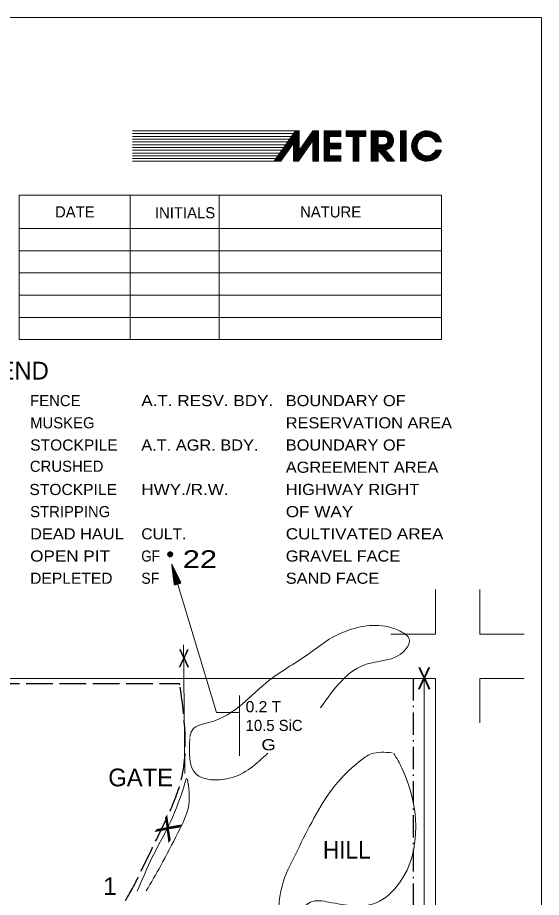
# Model space of a CAD drawing. Extents: x -496 to 480, y -450 to 700.
# Drawn here: x 214.3 to 450, y 303.7 to 700 of the extents above; entities that cross this region are included whole.
import ezdxf
from ezdxf.enums import TextEntityAlignment as Align

# ---------------------------------------------------------------- set-up
doc = ezdxf.new("R2010")
doc.units = 0
doc.header["$LTSCALE"] = 2
doc.linetypes.add('DOT_DASHED', pattern=[7.7, 5, -1.2, 0.3, -1.2])
doc.linetypes.add('LONG_DASHED', pattern=[7.5, 6, -1.5])
for name, color, linetype, lineweight in [('1', 7, 'Continuous', 13), ('2', 7, 'Continuous', 35), ('3', 7, 'Continuous', 13), ('4', 7, 'Continuous', 25)]:
    doc.layers.add(name, color=color, linetype=linetype, lineweight=lineweight)

msp = doc.modelspace()

# ---------------------------------------------------------------- linework, layer by layer
at = {"layer": '1'}
for p, q in [((339.376, 648.989), (265.976, 648.989)), ((338.501, 647.739), (265.976, 647.739)), ((337.626, 646.489), (265.976, 646.489)), ((329.726, 635.239), (339.376, 648.989)), ((340.976, 640.064), (347.226, 648.989)), ((349.726, 648.989), (347.226, 648.989)), ((349.726, 635.239), (349.726, 648.989)), ((354.726, 646.489), (354.726, 643.364)), ((362.226, 648.989), (362.226, 646.489)), ((362.226, 646.489), (365.351, 646.489)), ((367.851, 646.489), (370.976, 646.489)), ((379.026, 648.989), (373.476, 648.989)), ((376.601, 646.489), (379.151, 646.489)), ((376.601, 642.739), (376.601, 646.489)), ((336.751, 645.239), (265.976, 645.239)), ((335.876, 643.989), (265.976, 643.989)), ((335.001, 642.739), (265.976, 642.739)), ((332.776, 635.239), (338.476, 643.364)), ((338.476, 635.239), (338.476, 643.389)), ((340.676, 635.264), (347.226, 644.614)), ((347.226, 635.239), (347.226, 644.614)), ((376.601, 642.739), (379.151, 642.739)), ((402.426, 643.989), (405.076, 643.989)), ((334.126, 641.489), (265.976, 641.489)), ((333.251, 640.239), (265.976, 640.239)), ((332.376, 638.989), (265.976, 638.989)), ((354.726, 640.864), (354.726, 637.739)), ((376.601, 640.239), (380.726, 635.239)), ((376.601, 635.239), (376.601, 640.239)), ((379.801, 640.289), (383.951, 635.239)), ((402.426, 640.239), (405.101, 640.239)), ((331.501, 637.739), (265.976, 637.739)), ((330.626, 636.489), (265.976, 636.489)), ((329.726, 635.239), (265.976, 635.239)), ((329.726, 635.239), (332.776, 635.239)), ((338.476, 635.239), (340.676, 635.239)), ((349.726, 635.239), (347.226, 635.239)), ((352.226, 635.239), (359.726, 635.239)), ((380.726, 635.239), (383.951, 635.239)), ((404.983, 619.973), (214.983, 619.973)), ((214.983, 619.973), (214.983, 554.973)), ((264.983, 619.973), (264.983, 554.973)), ((304.983, 619.973), (304.983, 554.973)), ((404.983, 554.973), (404.983, 619.973)), ((214.983, 604.973), (404.983, 604.973)), ((214.983, 594.973), (404.983, 594.973)), ((214.983, 584.973), (404.983, 584.973)), ((214.983, 574.973), (404.983, 574.973)), ((214.983, 564.973), (404.983, 564.973)), ((214.983, 554.973), (404.983, 554.973)), ((402.281, 422.339), (402.281, 442.339)), ((422.281, 422.339), (422.281, 442.339)), ((402.281, 422.339), (382.281, 422.339)), ((422.281, 422.339), (442.281, 422.339)), ((422.281, 402.339), (442.281, 402.339)), ((422.281, 402.339), (422.281, 382.339))]:
    msp.add_line(p, q, dxfattribs=at)
for points in [[(449.983, -450.027), (449.983, 399.973), (449.983, 699.973), (-450.017, 699.973), (-450.017, 49.973), (-450.017, -450.027)], [(329.901, 635.339), (339.401, 648.889), (340.901, 648.889), (340.901, 639.839), (347.251, 648.839), (349.626, 648.889), (349.676, 635.339), (347.351, 635.314), (347.301, 644.789), (340.576, 635.339), (338.576, 635.314), (338.576, 643.539), (332.701, 635.339), (330.076, 635.314), (339.501, 648.739), (340.801, 648.739), (340.776, 639.664), (347.276, 648.664), (349.526, 648.739), (349.651, 635.564), (347.501, 635.464), (347.426, 644.989), (340.526, 635.489), (338.726, 635.439), (338.676, 643.764), (332.651, 635.464), (330.301, 635.439), (339.576, 648.539), (340.651, 648.564), (340.651, 639.489), (347.351, 648.489), (349.301, 648.564), (349.476, 635.739), (347.726, 635.639), (347.626, 645.314), (340.451, 635.714), (338.926, 635.639), (338.876, 644.139), (332.501, 635.689), (330.701, 635.639)], [(330.701, 635.639), (339.651, 648.239), (340.326, 648.264), (340.476, 639.239), (347.526, 648.239), (349.126, 648.289), (349.226, 635.939), (348.001, 635.939), (347.851, 645.664), (340.326, 635.989), (339.151, 635.864), (339.126, 644.464), (332.401, 635.939), (331.076, 635.839), (339.651, 647.914), (340.151, 647.914), (340.251, 638.889), (347.601, 647.964), (348.926, 648.014), (349.026, 636.164), (348.251, 636.139), (348.051, 646.014), (340.226, 636.239), (339.351, 636.089), (339.326, 644.789), (332.226, 636.164), (331.476, 636.064), (339.701, 647.664), (339.926, 647.689), (340.126, 638.764), (347.751, 647.839), (348.701, 647.739), (348.826, 636.364), (348.476, 636.364), (348.176, 646.314), (340.126, 636.464), (339.551, 636.339), (339.426, 645.114), (332.201, 636.339), (331.851, 636.289)], [(331.851, 636.289), (339.701, 647.264), (339.926, 638.564), (347.826, 647.614), (348.451, 647.589), (348.701, 636.589), (348.251, 646.639), (340.126, 636.689), (339.726, 636.589), (339.576, 645.539), (332.301, 636.639), (339.526, 646.714), (339.576, 645.814), (335.101, 640.239), (339.401, 646.164), (339.401, 645.914), (338.176, 644.289)], [(340.976, 640.039), (340.976, 648.989), (339.376, 648.989)], [(339.901, 638.414), (339.926, 636.839), (348.276, 646.889), (348.326, 647.439), (347.951, 647.439), (340.126, 638.539), (340.151, 637.314), (348.176, 647.064), (348.051, 647.214), (340.326, 638.539), (340.401, 637.839), (347.851, 646.839), (340.501, 638.639), (340.526, 638.389), (344.426, 642.914)], [(352.226, 635.239), (352.226, 648.989), (359.726, 648.989)], [(352.376, 648.914), (359.651, 648.864), (359.676, 646.614), (354.626, 646.589), (354.626, 643.289), (359.651, 643.289), (359.651, 640.989), (354.651, 640.939), (354.626, 637.614), (359.676, 637.639), (359.651, 635.339), (352.351, 635.314), (352.376, 648.789), (359.551, 648.739), (359.551, 646.764), (354.501, 646.714), (354.501, 643.214), (359.551, 643.164), (359.551, 641.114), (354.551, 641.064), (354.526, 637.439), (359.551, 637.514), (359.501, 635.439), (352.501, 635.439), (352.576, 648.639), (359.401, 648.564), (359.426, 646.914), (354.376, 646.839), (354.351, 643.064), (359.426, 643.039), (359.376, 641.289), (354.401, 641.239), (354.376, 637.239), (359.401, 637.339), (359.376, 635.589), (352.701, 635.614), (352.726, 648.439), (359.226, 648.414), (359.251, 647.064), (354.251, 647.039)], [(354.251, 647.039), (354.176, 642.864), (359.251, 642.864), (359.176, 641.439), (354.251, 641.389), (354.201, 637.064), (359.201, 637.114), (359.176, 635.739), (352.926, 635.814), (352.976, 648.214), (359.026, 648.239), (359.076, 647.289), (354.076, 647.214), (354.001, 642.689), (359.051, 642.664), (359.026, 641.639), (354.076, 641.564), (354.026, 636.864), (359.051, 636.939), (359.026, 635.989), (353.126, 636.039), (353.226, 647.989), (358.801, 648.039), (358.826, 647.464), (353.926, 647.389), (353.851, 642.489), (358.876, 642.539), (358.801, 641.814), (353.951, 641.689), (353.851, 636.714), (358.901, 636.764), (358.901, 636.214), (353.351, 636.214), (353.476, 647.714), (358.601, 647.889), (358.626, 647.639), (353.776, 647.514), (353.751, 642.364), (358.626, 642.389), (358.601, 642.014)], [(358.601, 642.014), (353.826, 641.864), (353.726, 636.564), (358.701, 636.639), (358.701, 636.389), (353.551, 636.439), (353.626, 641.989), (358.376, 642.164), (358.326, 642.289), (353.576, 642.264), (353.676, 647.564)], [(359.726, 648.989), (359.726, 646.489), (354.726, 646.489)], [(370.976, 646.489), (370.976, 648.989), (362.226, 648.989)], [(362.351, 648.864), (370.851, 648.889), (370.851, 646.639), (367.701, 646.639), (367.751, 635.414), (365.451, 635.314), (365.451, 646.564), (362.351, 646.589), (362.351, 648.764), (370.801, 648.789), (370.726, 646.789), (367.601, 646.764), (367.676, 635.539), (365.576, 635.414), (365.626, 646.739), (362.476, 646.739), (362.476, 648.639), (370.626, 648.639), (370.576, 646.989), (367.426, 646.864), (367.526, 635.739), (365.751, 635.614), (365.776, 646.864), (362.701, 646.939), (362.726, 648.439), (370.451, 648.489), (370.376, 647.114), (367.276, 646.989), (367.376, 635.914), (365.901, 635.789), (365.951, 647.064), (362.901, 647.114), (362.901, 648.264), (370.201, 648.289), (370.201, 647.364), (367.076, 647.189), (367.226, 636.114), (366.126, 635.989), (366.101, 647.264), (363.101, 647.314)], [(363.101, 647.314), (363.151, 648.089), (369.976, 648.164), (369.926, 647.489), (366.876, 647.364), (367.026, 636.339), (366.351, 636.239), (366.276, 647.439), (363.326, 647.514), (363.401, 647.939), (369.751, 648.039), (369.701, 647.714), (366.726, 647.539), (366.851, 636.564), (366.476, 636.489), (366.426, 647.664), (363.701, 647.664), (363.751, 647.839), (369.451, 647.914), (369.426, 647.814), (366.601, 647.664), (366.626, 636.689)], [(367.851, 646.489), (367.851, 635.239), (365.351, 635.239), (365.351, 646.489)], [(373.476, 648.989), (373.476, 635.239), (376.601, 635.239)], [(373.601, 648.914), (378.976, 648.889), (380.101, 648.739), (381.101, 648.364), (381.826, 647.789), (382.451, 647.189), (382.901, 646.414), (383.301, 645.389), (383.301, 644.439), (383.126, 643.214), (382.651, 642.314), (381.926, 641.489), (381.051, 640.889), (380.401, 640.639), (379.651, 640.389), (380.026, 639.714), (380.576, 639.189), (383.701, 635.339), (380.801, 635.314), (376.501, 640.464), (376.526, 635.339), (373.551, 635.314), (373.551, 648.864), (379.026, 648.789), (380.076, 648.639), (380.926, 648.314), (382.276, 647.214), (383.151, 645.364), (383.026, 643.314), (382.601, 642.464), (381.901, 641.614), (381.051, 640.989), (379.576, 640.464), (383.501, 635.414), (380.951, 635.439), (376.351, 640.739), (376.401, 635.489), (373.701, 635.439), (373.701, 648.739), (379.151, 648.664), (380.076, 648.489), (380.851, 648.189), (382.126, 647.139), (383.026, 645.389), (382.951, 643.539), (382.501, 642.564), (381.901, 641.739), (381.051, 641.114), (379.401, 640.614), (383.201, 635.564), (381.001, 635.564), (376.226, 640.889), (376.276, 635.614), (373.826, 635.539), (373.826, 648.614), (379.126, 648.489), (380.676, 648.089), (382.026, 647.139), (382.876, 645.439), (382.801, 643.664), (382.401, 642.664), (381.801, 641.889), (380.951, 641.189), (379.226, 640.764), (382.901, 635.689), (381.101, 635.689), (376.051, 641.064), (376.126, 635.789), (373.976, 635.689), (373.976, 648.439), (379.101, 648.364), (380.551, 647.989), (381.851, 647.089), (382.776, 645.439), (382.701, 643.764), (382.326, 642.889), (381.726, 642.064), (380.901, 641.339), (379.026, 640.939), (382.601, 635.789), (381.126, 635.814), (375.876, 641.239), (375.976, 635.939), (374.126, 635.864), (374.126, 648.239), (379.026, 648.239), (380.251, 647.914), (381.676, 647.014), (382.576, 645.414), (382.601, 643.914), (382.276, 642.989), (381.651, 642.214), (380.826, 641.514), (378.851, 641.064), (382.351, 635.939), (381.176, 635.989), (375.776, 641.514), (375.826, 636.089), (374.251, 636.014), (374.276, 648.039), (378.976, 648.114)], [(378.976, 648.114), (379.026, 648.114), (380.201, 647.764), (381.526, 646.939), (382.401, 645.489), (382.401, 643.964), (382.076, 643.114), (380.826, 641.764), (378.601, 641.264), (382.001, 636.114), (381.351, 636.114), (375.676, 641.789), (375.676, 636.264), (374.376, 636.189), (374.451, 647.864), (378.926, 647.939), (380.176, 647.689), (381.351, 646.914), (382.151, 645.414), (382.201, 644.014), (381.901, 643.214), (380.726, 641.989), (378.401, 641.389), (381.676, 636.314), (381.501, 636.189), (375.526, 642.064), (375.476, 636.414), (374.551, 636.339), (374.651, 647.739), (379.976, 647.614), (381.151, 646.914), (382.001, 645.414), (382.051, 644.139), (381.726, 643.339), (380.651, 642.139), (378.226, 641.589), (381.401, 636.464), (375.401, 642.364), (375.376, 636.614), (374.676, 636.539), (374.901, 647.589), (379.826, 647.414), (380.851, 646.889), (381.801, 645.439), (381.901, 644.389), (381.576, 643.539), (380.576, 642.414), (378.051, 641.739), (380.676, 637.364), (375.376, 642.614), (375.226, 636.739), (374.851, 636.739), (375.076, 647.339), (379.601, 647.314), (380.676, 646.839), (381.626, 645.414), (381.726, 644.464), (381.376, 643.589), (380.501, 642.589), (377.826, 641.864), (380.026, 638.189), (375.251, 642.889), (375.076, 636.939), (374.926, 636.989), (375.226, 647.189), (379.526, 647.139), (380.551, 646.714), (381.401, 645.414), (381.551, 644.614), (380.376, 642.739), (377.726, 642.039), (379.276, 639.239), (375.351, 643.039), (375.426, 646.989), (379.476, 646.989), (380.526, 646.639), (381.251, 645.489), (381.326, 644.614), (380.276, 642.914), (377.551, 642.239), (378.601, 640.139), (375.576, 643.139), (375.676, 646.839), (379.451, 646.839), (380.476, 646.514), (381.101, 645.414), (381.051, 644.489), (380.876, 645.464), (380.501, 646.039), (380.151, 646.339), (379.476, 646.514), (378.751, 646.639), (377.601, 646.614), (376.476, 646.614), (376.501, 642.714), (378.626, 642.664), (377.376, 642.339), (378.126, 640.764), (375.726, 643.164), (375.876, 646.714), (379.451, 646.714)], [(376.026, 646.614), (375.901, 643.214), (377.551, 641.614), (377.251, 642.364), (377.776, 642.614), (376.826, 642.614), (377.201, 642.164)], [(376.151, 646.564), (376.051, 643.314), (376.376, 643.064), (376.351, 646.564), (376.251, 643.389)], [(379.451, 646.714), (379.401, 646.739), (380.451, 646.289)], [(386.776, 648.839), (388.951, 648.864), (389.001, 635.364), (386.701, 635.364), (386.676, 648.739), (388.851, 648.764), (388.876, 635.489), (386.826, 635.439), (386.801, 648.614), (388.776, 648.639), (388.776, 635.664), (386.976, 635.589), (386.926, 648.464), (388.626, 648.464), (388.601, 635.764), (387.126, 635.764), (387.101, 648.364), (388.501, 648.364), (388.451, 635.939), (387.301, 635.964), (387.301, 648.214), (388.401, 648.214), (388.301, 636.089), (387.426, 636.089), (387.476, 648.064), (388.251, 648.039), (388.151, 636.214), (387.576, 636.214), (387.676, 647.914), (388.126, 647.889), (388.001, 636.339), (387.776, 636.389), (387.826, 647.764), (387.976, 647.714), (387.901, 636.539)], [(404.901, 644.089), (404.451, 645.189), (403.851, 646.164), (403.151, 646.914), (402.301, 647.639), (401.151, 648.289), (400.126, 648.614), (398.801, 648.814), (397.351, 648.689), (395.876, 648.339), (394.601, 647.639), (393.601, 646.764), (392.776, 645.664), (392.176, 644.564), (391.801, 642.964), (391.801, 641.264), (392.176, 639.789), (392.726, 638.564), (393.351, 637.739), (394.101, 637.014), (394.976, 636.389), (395.901, 635.914), (397.126, 635.489), (398.726, 635.389), (400.151, 635.589), (401.301, 635.989), (402.326, 636.564), (403.326, 637.414), (404.001, 638.264), (404.426, 639.139), (404.801, 640.064), (402.526, 640.089), (401.776, 638.989), (400.776, 638.289), (399.801, 637.814), (398.476, 637.564), (397.026, 637.839), (396.126, 638.289), (395.276, 638.939), (394.551, 639.939), (394.076, 641.189), (394.051, 642.814), (394.276, 643.889), (394.901, 644.889), (395.601, 645.614), (396.476, 646.164), (397.376, 646.489), (398.426, 646.614), (399.526, 646.489), (400.426, 646.214), (401.176, 645.764), (401.801, 645.239), (402.301, 644.664), (402.576, 644.139), (404.726, 644.164), (404.251, 645.214), (403.651, 646.164), (402.276, 647.489), (401.126, 648.114), (399.351, 648.614), (397.876, 648.564), (396.551, 648.339), (395.226, 647.814), (394.351, 647.264), (393.451, 646.339), (392.676, 645.139), (392.176, 643.939), (391.976, 642.239), (392.076, 640.689), (392.576, 639.164), (393.476, 637.864), (394.526, 636.864), (395.701, 636.164), (397.201, 635.639), (398.626, 635.514), (400.251, 635.764), (401.276, 636.089), (402.301, 636.789), (403.176, 637.439), (403.726, 638.164), (404.376, 639.239), (404.551, 639.964), (402.626, 639.989), (402.076, 639.064), (400.751, 638.139), (399.826, 637.689), (398.526, 637.389), (396.976, 637.739), (395.601, 638.439), (394.651, 639.639), (394.076, 640.764), (393.876, 642.139), (394.151, 643.989), (394.726, 644.964), (395.826, 646.014), (397.051, 646.539), (398.351, 646.789), (399.826, 646.614), (401.026, 646.064), (401.701, 645.614), (402.226, 645.014)], [(402.226, 645.014), (402.301, 645.014), (402.676, 644.239), (404.476, 644.264), (404.026, 645.314), (402.876, 646.664), (401.901, 647.489), (400.851, 648.089), (399.251, 648.514), (396.976, 648.264), (395.201, 647.614), (394.051, 646.639), (393.151, 645.614), (392.526, 644.239), (392.176, 642.439), (392.326, 640.539), (392.676, 639.489), (392.951, 638.864), (393.701, 637.864), (394.851, 636.839), (397.101, 635.814), (398.651, 635.664), (401.026, 636.164), (403.076, 637.564), (403.901, 638.814), (404.326, 639.814), (403.476, 639.789), (402.726, 639.839), (402.201, 638.889), (400.776, 637.964), (399.526, 637.414), (398.251, 637.264), (396.651, 637.714), (395.476, 638.364), (394.451, 639.714), (393.901, 640.864), (393.701, 642.264), (393.976, 643.889), (394.651, 645.264), (395.701, 646.214), (397.376, 646.789), (398.851, 646.914), (400.251, 646.614), (401.626, 645.914), (402.426, 645.164), (402.801, 644.439), (404.226, 644.414), (403.426, 645.739), (402.676, 646.614), (401.826, 647.314), (400.851, 647.939), (399.276, 648.314), (397.051, 648.089), (395.226, 647.364), (393.976, 646.314), (393.201, 645.414), (392.651, 643.839), (392.426, 642.514), (392.451, 641.239), (392.651, 640.089), (393.101, 639.039), (393.651, 638.239), (394.376, 637.564), (395.226, 636.839), (396.351, 636.314), (397.451, 635.914), (398.701, 635.839), (400.826, 636.364), (402.976, 637.639), (403.801, 638.964), (404.026, 639.714), (402.851, 639.664), (402.326, 638.814), (401.226, 638.164), (399.651, 637.239), (398.226, 637.114), (397.101, 637.389), (395.976, 637.889), (394.801, 638.989), (394.101, 640.014), (393.601, 641.664), (393.676, 643.264), (394.101, 644.689), (395.376, 646.214), (396.876, 646.764), (398.751, 647.064), (400.326, 646.764), (401.751, 646.089), (402.651, 645.189), (402.951, 644.539), (403.876, 644.614), (403.051, 645.989), (402.201, 646.789), (400.851, 647.739), (399.376, 648.189), (397.151, 647.889), (395.451, 647.239), (394.076, 646.164), (393.251, 645.039), (392.701, 643.014), (392.651, 641.564)], [(392.651, 641.564), (392.676, 641.614), (392.951, 639.914), (393.451, 638.964), (394.051, 638.214), (394.926, 637.289), (395.951, 636.764), (396.601, 636.389), (397.801, 636.039), (398.776, 635.989), (400.726, 636.464), (402.951, 637.739), (403.651, 639.064), (403.726, 639.564), (403.026, 639.539), (402.576, 638.814), (399.876, 637.114), (398.026, 637.014), (396.051, 637.664), (394.476, 639.139), (393.526, 641.439), (393.651, 643.889), (394.476, 645.514), (395.726, 646.539), (397.351, 646.989), (398.701, 647.239), (400.476, 646.939), (401.751, 646.339), (402.526, 645.664), (402.851, 645.114), (403.076, 644.739), (403.551, 644.789), (402.926, 645.989), (401.801, 646.914), (400.676, 647.639), (399.376, 648.039), (397.176, 647.789), (395.676, 647.164), (394.226, 646.139), (393.501, 645.039), (392.901, 643.314), (392.826, 641.639), (393.126, 639.989), (393.851, 638.689), (394.951, 637.514), (396.001, 636.989), (396.726, 636.564), (398.626, 636.139), (400.701, 636.614), (402.776, 637.864), (403.476, 639.064), (403.601, 639.464), (403.251, 639.389), (402.751, 638.739), (400.001, 637.014), (398.001, 636.889), (395.901, 637.564), (394.326, 639.064), (393.376, 641.464), (393.576, 643.939), (394.301, 645.589), (395.526, 646.689), (398.576, 647.339), (400.751, 647.089), (401.751, 646.489), (402.601, 645.914), (403.076, 645.039), (403.326, 644.914), (402.851, 645.939), (400.926, 647.289), (399.526, 647.889), (397.401, 647.714), (395.626, 647.039), (394.251, 646.039), (393.576, 644.889), (393.026, 643.239), (392.951, 641.714), (393.276, 640.314), (393.801, 639.139), (394.376, 638.339), (395.076, 637.639), (396.901, 636.764), (398.651, 636.314), (400.576, 636.789), (402.601, 637.914), (403.351, 639.139), (402.501, 638.339), (401.601, 637.789), (400.101, 636.864), (398.051, 636.764), (395.801, 637.439), (394.176, 639.064), (393.226, 641.539), (393.501, 644.014), (394.126, 645.639), (395.451, 646.739), (397.026, 647.189), (398.576, 647.489), (399.776, 647.389), (400.526, 647.289), (399.551, 647.639)], [(399.551, 647.639), (398.601, 647.639), (397.451, 647.489), (395.901, 647.064)], [(354.726, 640.864), (359.726, 640.864), (359.726, 643.364), (354.726, 643.364)], [(402.751, 638.439), (402.076, 637.814), (400.676, 637.089), (399.226, 636.639), (398.501, 636.639), (396.951, 636.914), (395.751, 637.364), (394.201, 638.764), (393.101, 641.589), (393.401, 643.964), (393.901, 645.289)], [(354.726, 637.739), (359.726, 637.739), (359.726, 635.239)], [(402.281, -402.333), (402.281, 402.339), (-402.391, 402.339)]]:
    msp.add_lwpolyline(points, dxfattribs=at)
msp.add_lwpolyline([(386.601, 635.239), (386.601, 648.989), (389.101, 648.989), (389.101, 635.239)], close=True, dxfattribs=at)
for centre, radius, start, end in [((379.076, 644.614), 4.375, 279.51602, 90.65478), ((379.051, 644.614), 1.875, 272.29061, 86.94712), ((398.476, 642.114), 6.875, 15.80251, 344.19749), ((398.476, 642.114), 4.375, 25.39292, 334.60708)]:
    msp.add_arc(centre, radius, start, end, dxfattribs=at)
at = {"layer": '2', "linetype": 'LONG_DASHED', "lineweight": 25}
for p in [(-126.758, 400), (287.345, 399.506)]:
    msp.add_line(p, (287.237, 400), dxfattribs=at)
at = {"layer": '2', "lineweight": 13}
msp.add_line((314.105, 367.559), (314.105, 394.618), dxfattribs=at)
msp.add_lwpolyline([(314.105, 387.041), (303.811, 387.041), (283.764, 453.605)], dxfattribs=at)
at = {"layer": '2', "lineweight": 25}
msp.add_lwpolyline([(283.764, 453.605), (284.923, 444.555), (287.796, 445.42)], close=True, dxfattribs=at)
msp.add_lwpolyline([(284.987, 444.651), (283.888, 453.193), (287.643, 445.502), (285.102, 444.72), (284.047, 452.664), (287.478, 445.604), (285.173, 444.876), (284.215, 452.105), (287.279, 445.697), (285.3, 445.016), (284.392, 451.466), (287.088, 445.826), (285.409, 445.219), (284.604, 450.699), (286.859, 445.91), (285.549, 445.43), (284.837, 449.872), (286.566, 446.041), (285.662, 445.667), (285.062, 448.957), (286.305, 446.233), (285.779, 445.956), (285.399, 447.89), (285.958, 446.433)], dxfattribs=at)
at = {"layer": '2'}
msp.add_circle((282.955, 458.25), 1, dxfattribs=at)
msp.add_spline([(282.944, 459.137), (283.674, 458.733), (283.826, 457.885), (283.141, 457.357), (282.332, 457.587), (282.045, 458.345), (282.293, 458.907), (282.866, 459.075), (283.54, 458.581), (283.523, 457.84), (283.006, 457.581), (282.484, 457.75), (282.259, 458.396), (282.843, 458.862), (283.281, 458.328), (283.242, 457.845), (282.613, 457.98), (282.759, 458.615), (283.051, 458.064)], degree=3, dxfattribs=at)
at = {"layer": '2', "linetype": 'LONG_DASHED', "lineweight": 25}
msp.add_spline([(254.05, 290.114), (264.26, 304.622), (270.894, 317.609), (281.508, 339.607), (287.876, 356.304), (287.345, 399.506)], degree=3, dxfattribs=at)
at = {"layer": '3'}
for p, q in [((288.946, 417.436), (289.578, 359.495)), ((397.281, -401.02), (397.281, 402.339))]:
    msp.add_line(p, q, dxfattribs=at)
at = {"layer": '3', "linetype": 'DOT_DASHED', "lineweight": 25}
msp.add_line((392.281, 402.339), (392.281, -396.11), dxfattribs=at)
at = {"layer": '3'}
for points in [[(291.812, 375.908), (292.823, 378.938), (300.913, 382.642), (327.542, 401.496), (346.081, 413.953), (354.508, 420.014), (363.272, 424.054), (385.519, 424.054), (390.575, 419.677), (388.216, 414.627), (371.699, 408.903), (350.623, 389.094)], [(326.882, 368.738), (309.677, 357.39), (294.508, 359.41), (291.812, 375.235)], [(383.644, 368.574), (387.241, 361.902), (386.213, 310.321), (375.679, 301.339), (354.355, 301.595), (346.133, 301.595), (343.307, 299.542), (339.196, 288.251), (337.141, 280.809), (334.058, 281.835), (331.746, 289.277), (333.287, 308.781), (339.453, 323.408), (346.647, 337.523), (355.383, 351.894), (368.486, 365.238), (373.367, 368.318), (382.873, 368.831)], [(268.184, 306.556), (275.087, 322.104), (284.03, 339.766), (290.331, 357.429)], [(272.179, 306.65), (278.745, 318.043), (286.469, 332.864), (291.347, 345.451), (290.737, 357.023)]]:
    msp.add_spline(points, degree=3, dxfattribs=at)

# ---------------------------------------------------------------- texts
at = {"layer": '1'}
for s, height, p in [('DATE', 5, (240.081, 609.973)), ('INITIALS', 5, (289.66, 609.584)), ('NATURE', 5, (355.16, 609.973)), ('LEGEND', 8, (206.378, 536.973))]:
    msp.add_text(s, height=height, dxfattribs=at).set_placement(p, align=Align.CENTER)
for s, p in [('FENCE', (219.983, 524.973)), ('MUSKEG', (219.983, 514.973)), ('CRUSHED', (219.856, 495.402)), ('STRIPPING', (219.983, 474.973))]:
    msp.add_text(s, height=5, dxfattribs=at).set_placement(p)
for s, width, p in [('A.T. RESV. BDY.', 1.15, (269.983, 524.973)), ('BOUNDARY OF', 1.1, (334.983, 524.973)), ('RESERVATION AREA', 1.1, (334.983, 514.973)), ('STOCKPILE', 1.05, (219.983, 504.973)), ('A.T. AGR. BDY.', 1.1, (269.983, 504.973)), ('BOUNDARY OF', 1.1, (334.983, 504.973)), ('AGREEMENT AREA', 1.1, (334.983, 494.973)), ('STOCKPILE', 1.05, (219.649, 484.941)), ('HWY./R.W.', 1.15, (269.983, 484.973)), ('HIGHWAY RIGHT', 1.1, (334.983, 484.973)), ('OF WAY', 1.15, (334.983, 474.973)), ('DEAD HAUL', 1.1, (219.983, 464.973)), ('CULT.', 1.05, (269.983, 464.973)), ('CULTIVATED AREA', 1.15, (334.983, 464.973)), ('OPEN PIT', 1.15, (219.983, 454.973)), ('GF', 0.9, (269.983, 454.973)), ('GRAVEL FACE', 1.1, (334.983, 454.973)), ('DEPLETED', 1.05, (219.983, 444.973)), ('SF', 0.95, (269.983, 444.973)), ('SAND FACE', 1.1, (334.983, 444.973))]:
    msp.add_text(s, height=5, dxfattribs=dict(at, width=width)).set_placement(p)
at = {"layer": '2'}
for s, width, p in [(' 22', 1.3, (304.065, 452.05)), ('  1', 1.05, (258.975, 304.781))]:
    msp.add_text(s, height=8, dxfattribs=dict(at, width=width)).set_placement(p, align=Align.RIGHT)
for s, width, p in [('0.2 T      ', 1.05, (316.921, 387.122)), ('  G        ', 1.25, (319.359, 369.98))]:
    msp.add_text(s, height=5, dxfattribs=dict(at, width=width)).set_placement(p)
msp.add_text('10.5 SiC   ', height=5, dxfattribs=at).set_placement((316.921, 378.686))
at = {"layer": '3', "width": 0.7}
for height, p in [(8, (289.159, 407.418)), (8, (289.159, 407.418)), (10, (397.26, 397.365))]:
    msp.add_text('X', height=height, dxfattribs=at).set_placement(p, align=Align.CENTER)
at = {"layer": '3', "width": 1.55}
msp.add_text('X', height=8, rotation=54.05, dxfattribs=at).set_placement((285.244, 332.376), align=Align.CENTER)
at = {"layer": '4'}
msp.add_text('GATE', height=8, dxfattribs=at).set_placement((269.696, 353.75), align=Align.CENTER)
at = {"layer": '4', "width": 0.95}
msp.add_text('HILL', height=8, dxfattribs=at).set_placement((362.42, 321.117), align=Align.CENTER)

doc.saveas('drawing.dxf')
